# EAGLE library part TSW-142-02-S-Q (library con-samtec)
THROUGH-HOLE .025" SQ POST HEADER Source: Samtec TSW.pdf
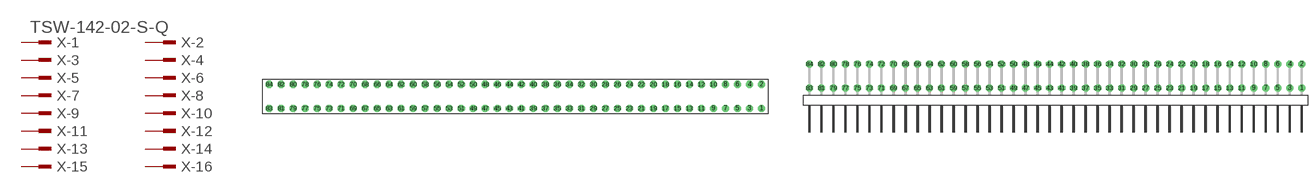
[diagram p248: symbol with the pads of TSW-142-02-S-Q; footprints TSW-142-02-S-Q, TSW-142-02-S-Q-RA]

Designator prefix X; gates -1=MPINV -2=MPIN -3=MPIN -4=MPIN -5=MPIN -6=MPIN -7=MPIN -8=MPIN -9=MPIN -10=MPIN -11=MPIN -12=MPIN -13=MPIN -14=MPIN -15=MPIN -16=MPIN -17=MPIN -18=MPIN -19=MPIN -20=MPIN -21=MPIN -22=MPIN -23=MPIN -24=MPIN -25=MPIN -26=MPIN -27=MPIN -28=MPIN -29=MPIN -30=MPIN -31=MPIN -32=MPIN -33=MPIN -34=MPIN -35=MPIN -36=MPIN -37=MPIN -38=MPIN -39=MPIN -40=MPIN -41=MPIN -42=MPIN -43=MPIN -44=MPIN -45=MPIN -46=MPIN -47=MPIN -48=MPIN -49=MPIN -50=MPIN -51=MPIN -52=MPIN -53=MPIN -54=MPIN -55=MPIN -56=MPIN -57=MPIN -58=MPIN -59=MPIN -60=MPIN -61=MPIN -62=MPIN -63=MPIN -64=MPIN -65=MPIN -66=MPIN -67=MPIN -68=MPIN -69=MPIN -70=MPIN -71=MPIN -72=MPIN -73=MPIN -74=MPIN -75=MPIN -76=MPIN -77=MPIN -78=MPIN -79=MPIN -80=MPIN -81=MPIN -82=MPIN -83=MPIN -84=MPIN

## TSW-142-02-S-Q (OC_FARNELL: unknown; OC_NEWARK: unknown)  [TSW-142-02-S-Q]
1  -1:1  pas
2  -2:1  pas
3  -3:1  pas
4  -4:1  pas
5  -5:1  pas
6  -6:1  pas
7  -7:1  pas
8  -8:1  pas
9  -9:1  pas
10  -10:1  pas
11  -11:1  pas
12  -12:1  pas
13  -13:1  pas
14  -14:1  pas
15  -15:1  pas
16  -16:1  pas
17  -17:1  pas
18  -18:1  pas
19  -19:1  pas
20  -20:1  pas
21  -21:1  pas
22  -22:1  pas
23  -23:1  pas
24  -24:1  pas
25  -25:1  pas
26  -26:1  pas
27  -27:1  pas
28  -28:1  pas
29  -29:1  pas
30  -30:1  pas
31  -31:1  pas
32  -32:1  pas
33  -33:1  pas
34  -34:1  pas
35  -35:1  pas
36  -36:1  pas
37  -37:1  pas
38  -38:1  pas
39  -39:1  pas
40  -40:1  pas
41  -41:1  pas
42  -42:1  pas
43  -43:1  pas
44  -44:1  pas
45  -45:1  pas
46  -46:1  pas
47  -47:1  pas
48  -48:1  pas
49  -49:1  pas
50  -50:1  pas
51  -51:1  pas
52  -52:1  pas
53  -53:1  pas
54  -54:1  pas
55  -55:1  pas
56  -56:1  pas
57  -57:1  pas
58  -58:1  pas
59  -59:1  pas
60  -60:1  pas
61  -61:1  pas
62  -62:1  pas
63  -63:1  pas
64  -64:1  pas
65  -65:1  pas
66  -66:1  pas
67  -67:1  pas
68  -68:1  pas
69  -69:1  pas
70  -70:1  pas
71  -71:1  pas
72  -72:1  pas
73  -73:1  pas
74  -74:1  pas
75  -75:1  pas
76  -76:1  pas
77  -77:1  pas
78  -78:1  pas
79  -79:1  pas
80  -80:1  pas
81  -81:1  pas
82  -82:1  pas
83  -83:1  pas
84  -84:1  pas

## TSW-142-02-S-Q-RA (OC_FARNELL: unknown; OC_NEWARK: unknown)  [TSW-142-02-S-Q-RA]
Pads as for TSW-142-02-S-Q

## Footprint TSW-142-02-S-Q (pad centres in mm)
THROUGH-HOLE .025" SQ POST HEADER Source: Samtec TSW.pdf
drill 1 pad 1.5 octagon: 1 52.07,-2.54; 2 52.07,2.54; 3 49.53,-2.54; 4 49.53,2.54; 5 46.99,-2.54; 6 46.99,2.54; 7 44.45,-2.54; 8 44.45,2.54; 9 41.91,-2.54; 10 41.91,2.54; 11 39.37,-2.54; 12 39.37,2.54; 13 36.83,-2.54; 14 36.83,2.54; 15 34.29,-2.54; 16 34.29,2.54; 17 31.75,-2.54; 18 31.75,2.54; 19 29.21,-2.54; 20 29.21,2.54; 21 26.67,-2.54; 22 26.67,2.54; 23 24.13,-2.54; 24 24.13,2.54; 25 21.59,-2.54; 26 21.59,2.54; 27 19.05,-2.54; 28 19.05,2.54; 29 16.51,-2.54; 30 16.51,2.54; 31 13.97,-2.54; 32 13.97,2.54; 33 11.43,-2.54; 34 11.43,2.54; 35 8.89,-2.54; 36 8.89,2.54; 37 6.35,-2.54; 38 6.35,2.54; 39 3.81,-2.54; 40 3.81,2.54; 41 1.27,-2.54; 42 1.27,2.54; 43 -1.27,-2.54; 44 -1.27,2.54; 45 -3.81,-2.54; 46 -3.81,2.54; 47 -6.35,-2.54; 48 -6.35,2.54; 49 -8.89,-2.54; 50 -8.89,2.54; 51 -11.43,-2.54; 52 -11.43,2.54; 53 -13.97,-2.54; 54 -13.97,2.54; 55 -16.51,-2.54; 56 -16.51,2.54; 57 -19.05,-2.54; 58 -19.05,2.54; 59 -21.59,-2.54; 60 -21.59,2.54; 61 -24.13,-2.54; 62 -24.13,2.54; 63 -26.67,-2.54; 64 -26.67,2.54; 65 -29.21,-2.54; 66 -29.21,2.54; 67 -31.75,-2.54; 68 -31.75,2.54; 69 -34.29,-2.54; 70 -34.29,2.54; 71 -36.83,-2.54; 72 -36.83,2.54; 73 -39.37,-2.54; 74 -39.37,2.54; 75 -41.91,-2.54; 76 -41.91,2.54; 77 -44.45,-2.54; 78 -44.45,2.54; 79 -46.99,-2.54; 80 -46.99,2.54; 81 -49.53,-2.54; 82 -49.53,2.54; 83 -52.07,-2.54; 84 -52.07,2.54

## Footprint TSW-142-02-S-Q-RA (pad centres in mm)
THROUGH-HOLE .025" SQ POST HEADER Source: Samtec TSW.pdf
drill 1 pad 1.5 octagon: 1 52.07,1.524; 2 52.07,6.604; 3 49.53,1.524; 4 49.53,6.604; 5 46.99,1.524; 6 46.99,6.604; 7 44.45,1.524; 8 44.45,6.604; 9 41.91,1.524; 10 41.91,6.604; 11 39.37,1.524; 12 39.37,6.604; 13 36.83,1.524; 14 36.83,6.604; 15 34.29,1.524; 16 34.29,6.604; 17 31.75,1.524; 18 31.75,6.604; 19 29.21,1.524; 20 29.21,6.604; 21 26.67,1.524; 22 26.67,6.604; 23 24.13,1.524; 24 24.13,6.604; 25 21.59,1.524; 26 21.59,6.604; 27 19.05,1.524; 28 19.05,6.604; 29 16.51,1.524; 30 16.51,6.604; 31 13.97,1.524; 32 13.97,6.604; 33 11.43,1.524; 34 11.43,6.604; 35 8.89,1.524; 36 8.89,6.604; 37 6.35,1.524; 38 6.35,6.604; 39 3.81,1.524; 40 3.81,6.604; 41 1.27,1.524; 42 1.27,6.604; 43 -1.27,1.524; 44 -1.27,6.604; 45 -3.81,1.524; 46 -3.81,6.604; 47 -6.35,1.524; 48 -6.35,6.604; 49 -8.89,1.524; 50 -8.89,6.604; 51 -11.43,1.524; 52 -11.43,6.604; 53 -13.97,1.524; 54 -13.97,6.604; 55 -16.51,1.524; 56 -16.51,6.604; 57 -19.05,1.524; 58 -19.05,6.604; 59 -21.59,1.524; 60 -21.59,6.604; 61 -24.13,1.524; 62 -24.13,6.604; 63 -26.67,1.524; 64 -26.67,6.604; 65 -29.21,1.524; 66 -29.21,6.604; 67 -31.75,1.524; 68 -31.75,6.604; 69 -34.29,1.524; 70 -34.29,6.604; 71 -36.83,1.524; 72 -36.83,6.604; 73 -39.37,1.524; 74 -39.37,6.604; 75 -41.91,1.524; 76 -41.91,6.604; 77 -44.45,1.524; 78 -44.45,6.604; 79 -46.99,1.524; 80 -46.99,6.604; 81 -49.53,1.524; 82 -49.53,6.604; 83 -52.07,1.524; 84 -52.07,6.604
